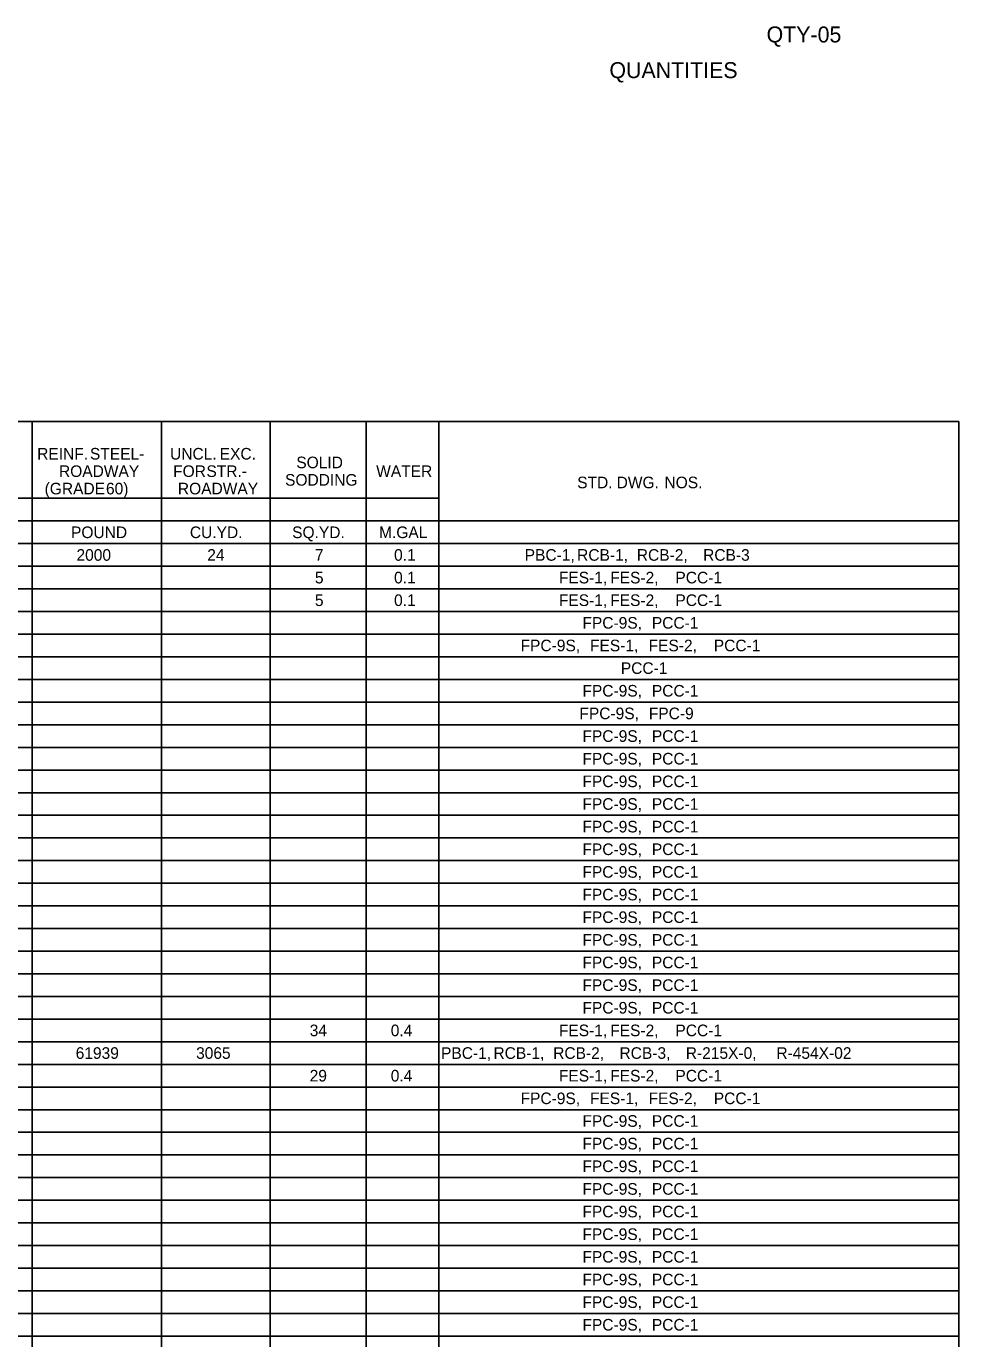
# Model space of a CAD drawing. Extents: x 1226564 to 1228153, y 151309 to 152340.
# Drawn here: x 1227810.6 to 1228152.7, y 151823.8 to 152305.5 of the extents above; entities that cross this region are included whole.
import ezdxf

# ---------------------------------------------------------------- set-up
doc = ezdxf.new("R2010")
doc.units = 0
doc.layers.add('R_Border', color=7, linetype='Continuous')
doc.layers.add('R_Dimension', color=7, linetype='Continuous')

msp = doc.modelspace()

# ---------------------------------------------------------------- linework, layer by layer
at = {"layer": 'R_Dimension'}
for p, q in [((1226563.55, 152160.49), (1228152.75, 152160.49)), ((1227812.79, 151354.44), (1227812.79, 152160.49)), ((1227860.16, 151354.44), (1227860.16, 152160.49)), ((1227900.05, 151354.44), (1227900.05, 152160.49)), ((1227935.36, 151354.44), (1227935.36, 152160.49)), ((1227961.95, 151354.44), (1227961.95, 152160.49)), ((1228152.75, 151354.44), (1228152.75, 152160.49)), ((1227254.62, 152132.24), (1227961.95, 152132.24)), ((1226840.79, 152123.93), (1228152.75, 152123.93)), ((1227443.42, 152123.93), (1227961.95, 152123.93)), ((1226563.55, 152115.62), (1228152.75, 152115.62)), ((1227961.95, 152115.62), (1228152.75, 152115.62)), ((1226563.55, 152107.31), (1228152.75, 152107.31)), ((1226563.55, 152099), (1228152.75, 152099)), ((1226563.55, 152090.69), (1228152.75, 152090.69)), ((1226563.55, 152082.38), (1228152.75, 152082.38)), ((1226563.55, 152074.07), (1228152.75, 152074.07)), ((1226563.55, 152065.76), (1228152.75, 152065.76)), ((1226563.55, 152057.45), (1228152.75, 152057.45)), ((1226563.55, 152049.14), (1228152.75, 152049.14)), ((1226563.55, 152040.83), (1228152.75, 152040.83)), ((1226563.55, 152032.52), (1228152.75, 152032.52)), ((1226563.55, 152024.21), (1228152.75, 152024.21)), ((1226563.55, 152015.9), (1228152.75, 152015.9)), ((1226563.55, 152007.59), (1228152.75, 152007.59)), ((1226563.55, 151999.28), (1228152.75, 151999.28)), ((1226563.55, 151990.97), (1228152.75, 151990.97)), ((1226563.55, 151982.66), (1228152.75, 151982.66)), ((1226563.55, 151974.35), (1228152.75, 151974.35)), ((1226563.55, 151966.04), (1228152.75, 151966.04)), ((1226563.55, 151957.73), (1228152.75, 151957.73)), ((1226563.55, 151949.42), (1228152.75, 151949.42)), ((1226563.55, 151941.11), (1228152.75, 151941.11)), ((1226563.55, 151932.8), (1228152.75, 151932.8)), ((1226563.55, 151924.49), (1228152.75, 151924.49)), ((1226563.55, 151916.18), (1228152.75, 151916.18)), ((1226563.55, 151907.87), (1228152.75, 151907.87)), ((1226563.55, 151899.56), (1228152.75, 151899.56)), ((1226563.55, 151891.25), (1228152.75, 151891.25)), ((1226563.55, 151882.94), (1228152.75, 151882.94)), ((1226563.55, 151874.64), (1228152.75, 151874.64)), ((1226563.55, 151866.33), (1228152.75, 151866.33)), ((1226563.55, 151858.02), (1228152.75, 151858.02)), ((1226563.55, 151849.71), (1228152.75, 151849.71)), ((1226563.55, 151841.4), (1228152.75, 151841.4)), ((1226563.55, 151833.09), (1228152.75, 151833.09)), ((1226563.55, 151824.78), (1228152.75, 151824.78))]:
    msp.add_line(p, q, dxfattribs=at)

# ---------------------------------------------------------------- texts
at = {"layer": 'R_Border'}
for s, height, p in [('QTY-05', 5.861, (1228082.24, 152299.55)), ('QUANTITIES', 5.862, (1228024.56, 152286.45))]:
    msp.add_text(s, height=height, dxfattribs=at).set_placement(p)
at = {"layer": 'R_Dimension'}
for s, height, p in [('REINF.', 4.261, (1227814.58, 152146.47)), (' STEEL-', 4.261, (1227832.36, 152146.47)), ('UNCL.', 4.261, (1227863.34, 152146.47)), (' EXC.', 4.261, (1227879.98, 152146.47)), ('SOLID', 4.261, (1227909.67, 152143.28)), ('ROADWAY', 4.261, (1227822.58, 152140.08)), ('FOR', 4.261, (1227864.47, 152140.08)), (' STR.-', 4.261, (1227875.1, 152140.08)), ('SODDING', 4.261, (1227905.54, 152136.88)), ('WATER', 4.261, (1227938.98, 152140.08)), ('(GRADE', 4.261, (1227817.32, 152133.69)), (' 60)', 4.261, (1227838.25, 152133.69)), ('ROADWAY', 4.261, (1227866.21, 152133.69)), ('STD.', 4.261, (1228012.74, 152135.93)), (' DWG.', 4.261, (1228025.63, 152135.93)), (' NOS.', 4.261, (1228043.18, 152135.93)), ('POUND', 4.261, (1227827, 152117.64)), ('CU.YD.', 4.261, (1227870.61, 152117.64)), ('SQ.YD.', 4.261, (1227908.14, 152117.64)), ('M.GAL', 4.261, (1227940.03, 152117.64)), ('2000', 4.261, (1227829.01, 152109.33)), ('24', 4.261, (1227876.98, 152109.33)), ('7', 4.26, (1227916.5, 152109.33)), ('0.1', 4.261, (1227945.54, 152109.33)), ('PBC-1,', 4.261, (1227993.47, 152109.33)), (' RCB-1,', 4.261, (1228011.12, 152109.33)), (' RCB-2,', 4.261, (1228033.03, 152109.33)), (' RCB-3', 4.261, (1228057.36, 152109.33)), ('5', 4.26, (1227916.5, 152101.02)), ('0.1', 4.261, (1227945.54, 152101.02)), ('FES-1,', 4.261, (1228006.03, 152101.02)), (' FES-2,', 4.261, (1228023.28, 152101.02)), (' PCC-1', 4.261, (1228047.2, 152101.02)), ('5', 4.26, (1227916.5, 152092.72)), ('0.1', 4.261, (1227945.54, 152092.72)), ('FES-1,', 4.261, (1228006.03, 152092.72)), (' FES-2,', 4.261, (1228023.28, 152092.72)), (' PCC-1', 4.261, (1228047.2, 152092.72)), ('FPC-9S,', 4.261, (1228014.67, 152084.41)), (' PCC-1', 4.261, (1228038.56, 152084.41)), ('FPC-9S,', 4.261, (1227991.96, 152076.1)), (' FES-1,', 4.261, (1228015.85, 152076.1)), (' FES-2,', 4.261, (1228037.36, 152076.1)), (' PCC-1', 4.261, (1228061.28, 152076.1)), ('PCC-1', 4.261, (1228028.75, 152067.79)), ('FPC-9S,', 4.261, (1228014.67, 152059.48)), (' PCC-1', 4.261, (1228038.56, 152059.48)), ('FPC-9S,', 4.261, (1228013.55, 152051.17)), (' FPC-9', 4.261, (1228037.44, 152051.17)), ('FPC-9S,', 4.261, (1228014.67, 152042.86)), (' PCC-1', 4.261, (1228038.56, 152042.86)), ('FPC-9S,', 4.261, (1228014.67, 152034.55)), (' PCC-1', 4.261, (1228038.56, 152034.55)), ('FPC-9S,', 4.261, (1228014.67, 152026.24)), (' PCC-1', 4.261, (1228038.56, 152026.24)), ('FPC-9S,', 4.261, (1228014.67, 152017.93)), (' PCC-1', 4.261, (1228038.56, 152017.93)), ('FPC-9S,', 4.261, (1228014.67, 152009.62)), (' PCC-1', 4.261, (1228038.56, 152009.62)), ('FPC-9S,', 4.261, (1228014.67, 152001.31)), (' PCC-1', 4.261, (1228038.56, 152001.31)), ('FPC-9S,', 4.261, (1228014.67, 151993)), (' PCC-1', 4.261, (1228038.56, 151993)), ('FPC-9S,', 4.261, (1228014.67, 151984.69)), (' PCC-1', 4.261, (1228038.56, 151984.69)), ('FPC-9S,', 4.261, (1228014.67, 151976.38)), (' PCC-1', 4.261, (1228038.56, 151976.38)), ('FPC-9S,', 4.261, (1228014.67, 151968.07)), (' PCC-1', 4.261, (1228038.56, 151968.07)), ('FPC-9S,', 4.261, (1228014.67, 151959.76)), (' PCC-1', 4.261, (1228038.56, 151959.76)), ('FPC-9S,', 4.261, (1228014.67, 151951.45)), (' PCC-1', 4.261, (1228038.56, 151951.45)), ('FPC-9S,', 4.261, (1228014.67, 151943.14)), (' PCC-1', 4.261, (1228038.56, 151943.14)), ('34', 4.261, (1227914.58, 151934.83)), ('0.4', 4.261, (1227944.33, 151934.83)), ('FES-1,', 4.261, (1228006.03, 151934.83)), (' FES-2,', 4.261, (1228023.28, 151934.83)), (' PCC-1', 4.261, (1228047.2, 151934.83)), ('61939', 4.261, (1227828.71, 151926.52)), ('3065', 4.261, (1227872.89, 151926.52)), ('PBC-1,', 4.261, (1227962.78, 151926.52)), (' RCB-1,', 4.261, (1227980.43, 151926.52)), (' RCB-2,', 4.261, (1228002.35, 151926.52)), (' RCB-3,', 4.261, (1228026.67, 151926.52)), (' R-215X-0,', 4.261, (1228051, 151926.52)), (' R-454X-02', 4.261, (1228084.25, 151926.52)), ('29', 4.261, (1227914.57, 151918.21)), ('0.4', 4.261, (1227944.33, 151918.21)), ('FES-1,', 4.261, (1228006.03, 151918.21)), (' FES-2,', 4.261, (1228023.28, 151918.21)), (' PCC-1', 4.261, (1228047.2, 151918.21)), ('FPC-9S,', 4.261, (1227991.96, 151909.9)), (' FES-1,', 4.261, (1228015.85, 151909.9)), (' FES-2,', 4.261, (1228037.36, 151909.9)), (' PCC-1', 4.261, (1228061.28, 151909.9)), ('FPC-9S,', 4.261, (1228014.67, 151901.59)), (' PCC-1', 4.261, (1228038.56, 151901.59)), ('FPC-9S,', 4.261, (1228014.67, 151893.28)), (' PCC-1', 4.261, (1228038.56, 151893.28)), ('FPC-9S,', 4.261, (1228014.67, 151884.97)), (' PCC-1', 4.261, (1228038.56, 151884.97)), ('FPC-9S,', 4.261, (1228014.67, 151876.66)), (' PCC-1', 4.261, (1228038.56, 151876.66)), ('FPC-9S,', 4.261, (1228014.67, 151868.35)), (' PCC-1', 4.261, (1228038.56, 151868.35)), ('FPC-9S,', 4.261, (1228014.67, 151860.04)), (' PCC-1', 4.261, (1228038.56, 151860.04)), ('FPC-9S,', 4.261, (1228014.67, 151851.73)), (' PCC-1', 4.261, (1228038.56, 151851.73)), ('FPC-9S,', 4.261, (1228014.67, 151843.42)), (' PCC-1', 4.261, (1228038.56, 151843.42)), ('FPC-9S,', 4.261, (1228014.67, 151835.11)), (' PCC-1', 4.261, (1228038.56, 151835.11)), ('FPC-9S,', 4.261, (1228014.67, 151826.8)), (' PCC-1', 4.261, (1228038.56, 151826.8))]:
    msp.add_text(s, height=height, dxfattribs=at).set_placement(p)

doc.saveas('drawing.dxf')
